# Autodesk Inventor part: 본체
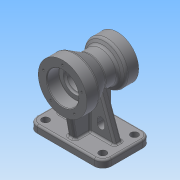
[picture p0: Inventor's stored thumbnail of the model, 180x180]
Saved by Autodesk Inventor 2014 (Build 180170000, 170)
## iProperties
Created: 2015-08
Part Number: 본체
Material: Generic
Document SubType Name: Modeling
Designer: SDA24
Density: 1 g/cm^3
Appearance: Default
Author: SDA24
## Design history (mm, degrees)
sketch "스케치2"
  geometry: L1 (-45, 0)-(45, 0); L2 (-45, 0)-(-45, 35); L3 (-45, 35)-(-25, 35); L4 (-25, 35)-(-19.804, 26); L5 (45, 0)-(45, 40); L6 (45, 40)-(25, 40); L7 (25, 40)-(0.751, 26); L8 (0.751, 26)-(-19.804, 26); 2 further points
  constraints: 16 end point, 5 perpendicular, 2 horizontal, 1 coincident, 1 midpoint
  dimensions: "d1" = 90 distance of L1.start L1.end; "d2" = 35 distance of L1.start L2.end; "d3" = 20 distance of L2.end L3.end; "d6" = 40 distance of L1.end L5.end; "d7" = 26 distance between parallel lines of L1 L8; "d9" = 20 distance of L5.end L6.end; "d10" = 60 deg angle of L4 L8
revolve "회전1" sketch "스케치2" stored, may be unused: angle "d11" = 90 deg
sketch "스케치5"
  geometry: C1 r 35 at (0, 0) reference; C2 r 20 at (0, 0)
  constraints: 1 centre point, 1 coincident
  dimensions: "d16" = 40 diameter of C2
fillet "모깎기1" dims "d24" = 5
node "작업 평면2"
sketch "스케치14"
  geometry: L1 (-40, -61)-(40, -61); L2 (40, -61)-(40, 61); L3 (40, 61)-(-40, 61); L4 (-40, 61)-(-40, -61); L5 (-40, -61)-(40, 61); L6 (40, -61)-(-40, 61); 1 further point
  constraints: 12 end point, 2 midpoint, 2 parallel, 1 horizontal, 1 perpendicular
  dimensions: "d52" = 80 distance of L3.end L2.end; "d53" = 122 distance of L2.end L1.end
extrude "돌출9" join sketch "스케치14" distance "d54" = 12; taper "d55" = 0 deg
sketch "스케치16"
  geometry: L1 (-36.7, -40)-(-30, -78); L2 (-1.912, -26.67)-(-23.84, -39.33) reference; L3 (16.917, -26)-(0.588, -26) reference; L4 (23.557, -32.5)-(21.247, -28.5) reference; L5 (40, -78)-(-40, -78) reference; L6 (30, -35)-(30, -78); L7 (-36.7, -40)-(-26.34, -40); L8 (27.887, -35)-(30, -35); L9 (-30, -78)-(30, -78); A1 r 5 centre (-26.34, -35) between (-26.34, -40) and (-23.84, -39.33) reference; A2 r 5 centre (0.588, -31) between (0.588, -26) and (-1.912, -26.67) reference; A3 r 5 centre (16.917, -31) between (21.247, -28.5) and (16.917, -26) reference; A4 r 5 centre (27.887, -30) between (23.557, -32.5) and (27.887, -35) reference; 1 further point
  constraints: 10 end point, 2 point on line, 1 collinear, 1 parallel, 1 perpendicular, 1 tangent, 1 vertical
  dimensions: "d59" = 80 deg angle of L5 L1; "d60" = 10 distance of L1.end L5.end; "d61" = 10 distance of L5.start L6.end
extrude "돌출10" join sketch "스케치16" stored distance "d62" = 12; taper "d63" = 0 deg
node "작업 평면3"
sketch "스케치18"
  geometry: 1 further point
sketch "스케치22" dims "d84" = 66
  geometry: L1 (0, 0)-(-33, 0); C1 r 40 at (0, 0) reference
  constraints: 2 end point, 1 coincident, 1 horizontal, 1 horizontal alignment, 2 other
hole "구멍1" sketch "스케치22" at (-33, 0) diameter "d85" = 3.242; stored, may be unused: countersink angle "d89" = 90 deg, drill point angle "d91" = 118 deg; dims "d86" = 10, "d87" = 4, "d88" = 2, "d90" = 13
sketch "스케치23" dims "d95" = 54
  geometry: L1 (0, 0)-(27, 0); C1 r 35 at (0, 0) reference
  constraints: 2 end point, 1 coincident, 1 horizontal, 1 horizontal alignment, 2 other
hole "구멍2" sketch "스케치23" at (27, 0) diameter "d96" = 3.242; stored, may be unused: countersink angle "d100" = 90 deg, drill point angle "d102" = 118 deg; dims "d97" = 10, "d98" = 4, "d99" = 2, "d101" = 13
node "작업 평면5"
sketch "스케치24"
  geometry: L1 (-12, 122)-(-12, 0) reference; L2 (-12, 14)-(-77.902, 37.986); L3 (-12, 108)-(-77.902, 84.014); L4 (-12, 14)-(-12, 108); A1 r 26 centre (-90, 61) between (-64, 61) and (-77.902, 37.986) reference; A2 r 26 centre (-90, 61) between (-77.902, 37.986) and (-77.902, 84.014); 1 further point
  constraints: 6 end point, 5 point on circle, 2 point on line, 1 centre point, 1 collinear
  dimensions: "d112" = 70 deg angle of L4 L2; "d113" = 70 deg angle of L1 L3; "d114" = 47 vertical distance of L2.start point (-90, 61); "d115" = 47 vertical distance of L3.start point (-90, 61)
extrude "돌출13" join sketch "스케치24" stored distance "d116" = 12; taper "d117" = 0 deg
sketch "스케치25"
  geometry: L1 (-40, -78)-(40, -78) reference; 3 further points
  constraints: 1 other
  dimensions: "d118" = 24 distance from line of point (-14, -54) L1; "d119" = 16 horizontal distance of point (-14, -54) point (-30, -78)
feature "엠보싱1" sketch "스케치25" dims "d1" = 90, "d120" = 0.5, "d121" = 0
sketch "스케치26"
  geometry: L1 (-12, 122)-(-12, 0) reference; L2 (-36.002, 31)-(-30, 31); L3 (-30, 43)-(-36.002, 43); A1 r 29.03 centre (-90, 61) between (-60.97, 61) and (-74.207, 85.359) reference; A2 r 6 centre (-30, 37) between (-30, 31) and (-30, 43); A3 r 6 centre (-36.002, 37) between (-36.002, 43) and (-36.002, 31)
  constraints: 4 end point, 4 point on circle, 2 centre point, 2 tangent, 1 horizontal alignment, 1 parallel
  dimensions: "d132" = 6 radius of A3; "d133" = 6 radius of A2; "d134" = 24 vertical distance of A1.centre A2.centre; "d135" = 18 distance from line of A2.centre L1; "d137" = 12 distance between parallel lines of L3 L2; "d138" = 6.00211 distance of A2.centre A3.centre
extrude "돌출14" cut sketch "스케치26" stored distance "d139" = 12; taper "d140" = 0 deg
fillet "모깎기2" dims "d141" = 14
sketch "스케치28"
  geometry: L1 (26, 47)-(-26, 47); L2 (-26, 47)-(-26, -47); L3 (-26, -47)-(26, -47); L4 (26, -47)-(26, 47); L5 (26, 47)-(-26, -47); L6 (-26, 47)-(26, -47); A1 r 14 centre (26, -47) between (26, -61) and (40, -47) reference; A2 r 14 centre (26, 47) between (40, 47) and (26, 61) reference; A3 r 14 centre (-26, 47) between (-26, 61) and (-40, 47) reference; A4 r 14 centre (-26, -47) between (-40, -47) and (-26, -61) reference; 1 further point
  constraints: 12 end point, 2 midpoint, 2 parallel, 1 horizontal, 1 perpendicular
  dimensions: "d142" = 52 distance of L3.end L2.end; "d143" = 94 distance of L1.end L2.end
hole "구멍3" sketch "스케치28" at (-26, -47), (26, -47), (26, 47), (-26, 47) diameter "d144" = 12; stored, may be unused: countersink angle "d148" = 90 deg, drill point angle "d150" = 0 deg; dims "d145" = 12, "d146" = 4, "d147" = 2, "d149" = 13
fillet "모깎기3" dims "d151" = 3
fillet "모깎기4" dims "d152" = 3
sketch "스케치29"
  geometry: C1 r 40 at (0, 0) reference; C2 r 26 at (0, 0)
  constraints: 1 centre point, 1 coincident
  dimensions: "d156" = 52 diameter of C2
extrude "돌출15" cut sketch "스케치29" distance "d157" = 20; taper "d158" = 0 deg
sketch "스케치30"
  geometry: C1 r 26 at (0, 0) reference; C2 r 19 at (0, 0)
  constraints: 1 centre point, 1 coincident
  dimensions: "d159" = 38 diameter of C2
extrude "돌출16" cut sketch "스케치30" distance "d160" = 3; taper "d161" = 0 deg
fillet "모깎기8" dims "d162" = 3
extrude "돌출17" cut sketch "스케치5" distance "d163" = 17; taper "d164" = 0 deg
sketch "스케치31"
  geometry: C1 r 20 at (0, 0) reference; C2 r 16 at (0, 0)
  constraints: 1 centre point, 1 coincident
  dimensions: "d165" = 32 diameter of C2
extrude "돌출18" cut sketch "스케치31" stored distance "d166" = 17; taper "d167" = 0 deg
fillet "모깎기9" dims "d168" = 0.3
chamfer "모따기1" distance "d169" = 1; stored, may be unused: second distance "d170" = 2, angle "d171" = 45 deg
node "솔리드1"
mirror "대칭1"
pattern_circular "원형 패턴3" dims angle "d173" = 360 deg
pattern_circular "원형 패턴4" dims angle "d176" = 360 deg
other parameters: "d76" = -45
